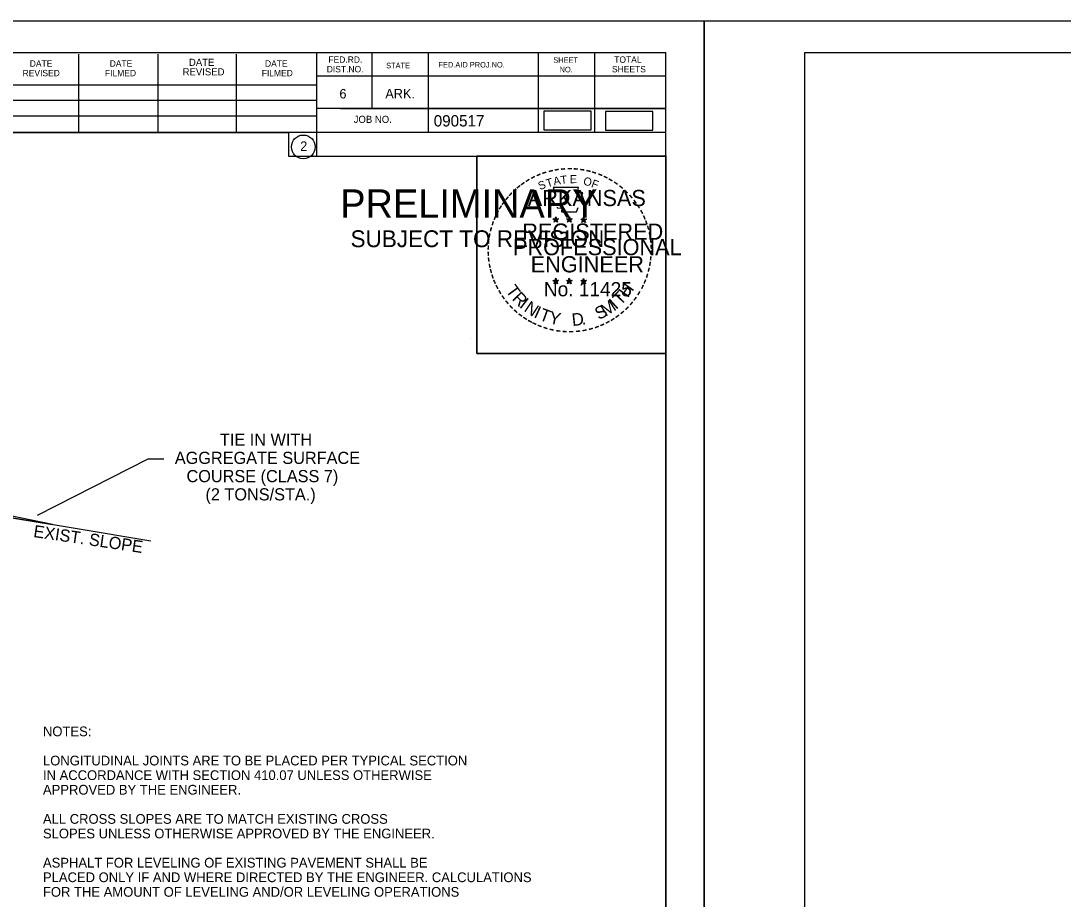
# Model space of a CAD drawing. Extents: x 2263886 to 2266026, y -3122850 to -3121850.
# Drawn here: x 2265483.5 to 2265547.8, y -3122391.3 to -3122337.2 of the extents above; entities that cross this region are included whole.
import ezdxf

# ---------------------------------------------------------------- set-up
doc = ezdxf.new("R2010")
doc.units = 0
for name, color, linetype in [('_CIVIL_CONSTRUCTION', 7, 'Continuous'), ('R_Border PE', 7, 'Continuous'), ('R_Border Prem', 7, 'Continuous'), ('R_Draft', 7, 'Continuous'), ('R_Vert Alg', 7, 'Continuous')]:
    doc.layers.add(name, color=color, linetype=linetype)

msp = doc.modelspace()

# ---------------------------------------------------------------- linework, layer by layer
at = {"layer": '_CIVIL_CONSTRUCTION'}
for p, q in [((2265359.025, -3122337.151), (2265525.692, -3122337.151)), ((2265525.695, -3122337.151), (2265692.362, -3122337.151)), ((2265511.332, -3122356.73), (2265511.332, -3122356.73))]:
    msp.add_line(p, q, dxfattribs=at)
for points in [[(2265359.022, -3122337.151), (2265525.692, -3122337.151), (2265525.692, -3122443.82), (2265359.022, -3122443.82)], [(2265525.692, -3122337.151), (2265692.362, -3122337.151), (2265692.362, -3122443.82), (2265525.692, -3122443.82)], [(2265482.186, -3122339.098), (2265482.186, -3122344.038), (2265500.052, -3122344.038), (2265500.052, -3122345.498), (2265511.651, -3122345.498), (2265511.651, -3122357.664), (2265523.316, -3122357.664), (2265523.316, -3122441.828), (2265365.226, -3122441.828), (2265365.226, -3122339.098)], [(2265648.856, -3122339.098), (2265648.856, -3122344.038), (2265666.722, -3122344.038), (2265666.722, -3122345.498), (2265678.321, -3122345.498), (2265678.321, -3122357.664), (2265689.986, -3122357.664), (2265689.986, -3122441.828), (2265531.896, -3122441.828), (2265531.896, -3122339.098)], [(2265511.651, -3122345.482), (2265523.316, -3122345.482), (2265523.316, -3122357.664), (2265511.651, -3122357.664)]]:
    msp.add_lwpolyline(points, close=True, dxfattribs=at)
at = {"layer": 'R_Border PE'}
for p, q in [((2265516.357, -3122349.375), (2265516.532, -3122349.431)), ((2265516.357, -3122349.375), (2265516.484, -3122349.398)), ((2265516.357, -3122349.375), (2265516.476, -3122349.436)), ((2265516.424, -3122349.579), (2265516.532, -3122349.431)), ((2265516.424, -3122349.579), (2265516.487, -3122349.457)), ((2265516.424, -3122349.579), (2265516.531, -3122349.471)), ((2265516.532, -3122349.248), (2265516.511, -3122349.374)), ((2265516.638, -3122349.579), (2265516.531, -3122349.472)), ((2265516.532, -3122349.431), (2265516.532, -3122349.248)), ((2265516.532, -3122349.248), (2265516.556, -3122349.373)), ((2265516.705, -3122349.375), (2265516.532, -3122349.431)), ((2265516.638, -3122349.579), (2265516.532, -3122349.431)), ((2265516.705, -3122349.375), (2265516.562, -3122349.4)), ((2265516.638, -3122349.579), (2265516.57, -3122349.434)), ((2265516.705, -3122349.375), (2265516.603, -3122349.426)), ((2265517.192, -3122349.375), (2265517.367, -3122349.431)), ((2265517.192, -3122349.375), (2265517.319, -3122349.398)), ((2265517.192, -3122349.375), (2265517.311, -3122349.436)), ((2265517.259, -3122349.579), (2265517.367, -3122349.431)), ((2265517.259, -3122349.579), (2265517.322, -3122349.457)), ((2265517.259, -3122349.579), (2265517.366, -3122349.471)), ((2265517.367, -3122349.248), (2265517.346, -3122349.374)), ((2265517.473, -3122349.579), (2265517.366, -3122349.472)), ((2265517.367, -3122349.431), (2265517.367, -3122349.248)), ((2265517.367, -3122349.248), (2265517.391, -3122349.373)), ((2265517.54, -3122349.375), (2265517.367, -3122349.431)), ((2265517.473, -3122349.579), (2265517.367, -3122349.431)), ((2265517.54, -3122349.375), (2265517.397, -3122349.4)), ((2265517.473, -3122349.579), (2265517.405, -3122349.434)), ((2265517.54, -3122349.375), (2265517.438, -3122349.426)), ((2265518.074, -3122349.381), (2265518.249, -3122349.437)), ((2265518.074, -3122349.381), (2265518.201, -3122349.404)), ((2265518.074, -3122349.381), (2265518.193, -3122349.442)), ((2265518.141, -3122349.585), (2265518.249, -3122349.437)), ((2265518.141, -3122349.585), (2265518.204, -3122349.463)), ((2265518.141, -3122349.585), (2265518.248, -3122349.477)), ((2265518.249, -3122349.254), (2265518.228, -3122349.38)), ((2265518.355, -3122349.585), (2265518.248, -3122349.478)), ((2265518.249, -3122349.437), (2265518.249, -3122349.254)), ((2265518.249, -3122349.254), (2265518.273, -3122349.379)), ((2265518.422, -3122349.381), (2265518.249, -3122349.437)), ((2265518.355, -3122349.585), (2265518.249, -3122349.437)), ((2265518.422, -3122349.381), (2265518.279, -3122349.406)), ((2265518.355, -3122349.585), (2265518.287, -3122349.44)), ((2265518.422, -3122349.381), (2265518.32, -3122349.432)), ((2265516.355, -3122353.162), (2265516.53, -3122353.217)), ((2265516.355, -3122353.162), (2265516.482, -3122353.184)), ((2265516.355, -3122353.162), (2265516.474, -3122353.223)), ((2265516.422, -3122353.366), (2265516.53, -3122353.217)), ((2265516.422, -3122353.366), (2265516.485, -3122353.244)), ((2265516.422, -3122353.366), (2265516.529, -3122353.257)), ((2265516.53, -3122353.035), (2265516.509, -3122353.161)), ((2265516.636, -3122353.366), (2265516.529, -3122353.259)), ((2265516.53, -3122353.217), (2265516.53, -3122353.035)), ((2265516.53, -3122353.035), (2265516.554, -3122353.16)), ((2265516.703, -3122353.162), (2265516.53, -3122353.217)), ((2265516.636, -3122353.366), (2265516.53, -3122353.217)), ((2265516.703, -3122353.162), (2265516.56, -3122353.186)), ((2265516.636, -3122353.366), (2265516.568, -3122353.22)), ((2265516.703, -3122353.162), (2265516.601, -3122353.213)), ((2265517.19, -3122353.162), (2265517.364, -3122353.217)), ((2265517.19, -3122353.162), (2265517.316, -3122353.184)), ((2265517.19, -3122353.162), (2265517.308, -3122353.223)), ((2265517.256, -3122353.366), (2265517.364, -3122353.217)), ((2265517.256, -3122353.366), (2265517.319, -3122353.244)), ((2265517.256, -3122353.366), (2265517.363, -3122353.257)), ((2265517.364, -3122353.035), (2265517.344, -3122353.161)), ((2265517.471, -3122353.366), (2265517.363, -3122353.259)), ((2265517.364, -3122353.217), (2265517.364, -3122353.035)), ((2265517.364, -3122353.035), (2265517.389, -3122353.16)), ((2265517.538, -3122353.162), (2265517.364, -3122353.217)), ((2265517.471, -3122353.366), (2265517.364, -3122353.217)), ((2265517.538, -3122353.162), (2265517.395, -3122353.186)), ((2265517.471, -3122353.366), (2265517.402, -3122353.22)), ((2265517.538, -3122353.162), (2265517.436, -3122353.213)), ((2265518.073, -3122353.167), (2265518.248, -3122353.222)), ((2265518.073, -3122353.167), (2265518.2, -3122353.189)), ((2265518.073, -3122353.167), (2265518.192, -3122353.228)), ((2265518.14, -3122353.371), (2265518.248, -3122353.222)), ((2265518.14, -3122353.371), (2265518.203, -3122353.249)), ((2265518.14, -3122353.371), (2265518.247, -3122353.262)), ((2265518.248, -3122353.04), (2265518.227, -3122353.166)), ((2265518.354, -3122353.371), (2265518.247, -3122353.264)), ((2265518.248, -3122353.222), (2265518.248, -3122353.04)), ((2265518.248, -3122353.04), (2265518.272, -3122353.165)), ((2265518.421, -3122353.167), (2265518.248, -3122353.222)), ((2265518.354, -3122353.371), (2265518.248, -3122353.222)), ((2265518.421, -3122353.167), (2265518.278, -3122353.191)), ((2265518.354, -3122353.371), (2265518.286, -3122353.225)), ((2265518.421, -3122353.167), (2265518.319, -3122353.218))]:
    msp.add_line(p, q, dxfattribs=at)
for points in [[(2265516.378, -3122347.436), (2265516.512, -3122347.85)], [(2265518.133, -3122347.897), (2265518.204, -3122347.755), (2265517.862, -3122347.767), (2265517.936, -3122347.436), (2265516.378, -3122347.436)], [(2265516.624, -3122348.648), (2265516.624, -3122348.691), (2265516.905, -3122348.701), (2265516.878, -3122348.937), (2265517.813, -3122348.937), (2265517.914, -3122348.669)], [(2265516.532, -3122349.248), (2265516.638, -3122349.579), (2265516.357, -3122349.375), (2265516.705, -3122349.375), (2265516.424, -3122349.579), (2265516.532, -3122349.248)], [(2265517.367, -3122349.248), (2265517.473, -3122349.579), (2265517.192, -3122349.375), (2265517.54, -3122349.375), (2265517.259, -3122349.579), (2265517.367, -3122349.248)], [(2265518.249, -3122349.254), (2265518.355, -3122349.585), (2265518.074, -3122349.381), (2265518.422, -3122349.381), (2265518.141, -3122349.585), (2265518.249, -3122349.254)], [(2265516.53, -3122353.035), (2265516.636, -3122353.366), (2265516.355, -3122353.162), (2265516.703, -3122353.162), (2265516.422, -3122353.366), (2265516.53, -3122353.035)], [(2265517.364, -3122353.035), (2265517.471, -3122353.366), (2265517.19, -3122353.162), (2265517.538, -3122353.162), (2265517.256, -3122353.366), (2265517.364, -3122353.035)], [(2265518.248, -3122353.04), (2265518.354, -3122353.371), (2265518.073, -3122353.167), (2265518.421, -3122353.167), (2265518.14, -3122353.371), (2265518.248, -3122353.04)]]:
    msp.add_lwpolyline(points, dxfattribs=at)
for centre, radius in [((2265516.531, -3122349.431), 0.0861), ((2265516.531, -3122349.431), 0.0723), ((2265516.531, -3122349.431), 0.0579), ((2265516.531, -3122349.431), 0.0495), ((2265516.531, -3122349.431), 0.0374), ((2265516.531, -3122349.431), 0.0248), ((2265516.531, -3122349.431), 0.0148), ((2265517.366, -3122349.431), 0.0861), ((2265517.366, -3122349.431), 0.0723), ((2265517.366, -3122349.431), 0.0579), ((2265517.366, -3122349.431), 0.0495), ((2265517.366, -3122349.431), 0.0374), ((2265517.366, -3122349.431), 0.0248), ((2265517.366, -3122349.431), 0.0148), ((2265518.248, -3122349.437), 0.0861), ((2265518.248, -3122349.437), 0.0723), ((2265518.248, -3122349.437), 0.0579), ((2265518.248, -3122349.437), 0.0495), ((2265518.248, -3122349.437), 0.0374), ((2265518.248, -3122349.437), 0.0248), ((2265518.248, -3122349.437), 0.0148), ((2265516.529, -3122353.217), 0.0861), ((2265516.529, -3122353.217), 0.0723), ((2265516.529, -3122353.217), 0.0579), ((2265516.529, -3122353.217), 0.0495), ((2265516.529, -3122353.217), 0.0374), ((2265516.529, -3122353.217), 0.0248), ((2265516.529, -3122353.217), 0.0148), ((2265517.364, -3122353.217), 0.0861), ((2265517.364, -3122353.217), 0.0723), ((2265517.364, -3122353.217), 0.0579), ((2265517.364, -3122353.217), 0.0495), ((2265517.364, -3122353.217), 0.0374), ((2265517.364, -3122353.217), 0.0248), ((2265517.364, -3122353.217), 0.0148), ((2265518.247, -3122353.222), 0.0861), ((2265518.247, -3122353.222), 0.0723), ((2265518.247, -3122353.222), 0.0579), ((2265518.247, -3122353.222), 0.0495), ((2265518.247, -3122353.222), 0.0374), ((2265518.247, -3122353.222), 0.0248), ((2265518.247, -3122353.222), 0.0148)]:
    msp.add_circle(centre, radius, dxfattribs=at)
at = {"layer": 'R_Border Prem'}
for p, q in [((2265485.48, -3122368.228), (2265481.556, -3122367.404)), ((2265491.562, -3122369.242), (2265481.556, -3122367.574)), ((2265481.556, -3122367.574), (2265485.48, -3122368.228))]:
    msp.add_line(p, q, dxfattribs=at)
msp.add_lwpolyline([(2265492.359, -3122364.182), (2265491.359, -3122364.182), (2265484.548, -3122367.669)], dxfattribs=at)
at = {"layer": 'R_Draft'}
for p, q in [((2265365.226, -3122339.098), (2265523.316, -3122339.098)), ((2265487.116, -3122344.038), (2265487.116, -3122339.198)), ((2265491.996, -3122344.038), (2265491.996, -3122339.198)), ((2265496.836, -3122344.038), (2265496.836, -3122339.198)), ((2265501.766, -3122339.098), (2265501.766, -3122345.498)), ((2265505.186, -3122339.098), (2265505.186, -3122342.568)), ((2265508.656, -3122339.098), (2265508.656, -3122344.038)), ((2265515.446, -3122339.098), (2265515.446, -3122344.038)), ((2265518.916, -3122339.098), (2265518.916, -3122344.038)), ((2265523.316, -3122441.828), (2265523.316, -3122339.098)), ((2265531.896, -3122339.098), (2265689.986, -3122339.098)), ((2265531.896, -3122441.828), (2265531.896, -3122339.098)), ((2265482.186, -3122341.108), (2265501.766, -3122341.108)), ((2265523.316, -3122340.568), (2265501.766, -3122340.568)), ((2265523.316, -3122340.558), (2265523.316, -3122340.558)), ((2265482.186, -3122342.038), (2265501.766, -3122342.038)), ((2265482.186, -3122343.008), (2265501.766, -3122343.008)), ((2265523.316, -3122342.568), (2265501.766, -3122342.568)), ((2265503.246, -3122342.568), (2265523.316, -3122342.568)), ((2265523.316, -3122344.038), (2265482.186, -3122344.038)), ((2265501.766, -3122345.498), (2265523.316, -3122345.498))]:
    msp.add_line(p, q, dxfattribs=at)
msp.add_circle((2265500.959, -3122344.93), 0.733, dxfattribs=at)
at = {"layer": 'R_Vert Alg'}
for points in [[(2265515.789, -3122343.868), (2265518.706, -3122343.868), (2265518.706, -3122342.713), (2265515.789, -3122342.713)], [(2265519.604, -3122343.897), (2265522.521, -3122343.897), (2265522.521, -3122342.741), (2265519.604, -3122342.741)]]:
    msp.add_lwpolyline(points, close=True, dxfattribs=at)

# ---------------------------------------------------------------- texts
at = {"layer": 'R_Border PE'}
for s, height, rotation, p in [('-', 0.8, 10.21935, (2265516.465, -3122346.671)), ('-', 0.8, 5.89682, (2265516.83, -3122346.616)), ('-', 0.8, 0.18623, (2265517.216, -3122346.58)), ('-', 0.8, 357.74304, (2265517.577, -3122346.587)), ('-', 0.8, 352.16172, (2265517.949, -3122346.615)), ('-', 0.8, 34.06357, (2265514.819, -3122347.351)), ('-', 0.8, 28.79182, (2265515.118, -3122347.166)), ('-', 0.8, 24.30721, (2265515.434, -3122347.007)), ('-', 0.8, 19.17608, (2265515.751, -3122346.873)), ('T', 0.5, 16.4036, (2265516.012, -3122347.432)), ('-', 0.8, 13.63015, (2265516.126, -3122346.752)), ('A', 0.5, 11.21318, (2265516.425, -3122347.306)), ('T', 0.5, 6.02276, (2265516.849, -3122347.223)), ('E', 0.5, 0.83234, (2265517.402, -3122347.168)), ('O', 0.5, 350.4515, (2265518.204, -3122347.273)), ('-', 0.8, 347.20489, (2265518.309, -3122346.672)), ('F', 0.5, 340.07066, (2265518.681, -3122347.387)), ('-', 0.8, 342.3362, (2265518.626, -3122346.749)), ('-', 0.8, 337.85509, (2265518.994, -3122346.861)), ('-', 0.8, 334.12109, (2265519.309, -3122346.996)), ('-', 0.8, 329.64089, (2265519.599, -3122347.138)), ('-', 0.8, 42.96224, (2265514.076, -3122347.946)), ('-', 0.8, 38.95066, (2265514.292, -3122347.737)), ('-', 0.8, 36.23174, (2265514.53, -3122347.548)), ('S', 0.5, 21.59401, (2265515.555, -3122347.597)), ('-', 0.8, 325.86266, (2265519.92, -3122347.318)), ('-', 0.8, 320.52971, (2265520.225, -3122347.531)), ('-', 0.8, 315.57859, (2265520.525, -3122347.775)), ('-', 0.8, 50.61417, (2265513.65, -3122348.428)), ('-', 0.8, 48.42305, (2265513.852, -3122348.185)), ('-', 0.8, 309.87973, (2265520.809, -3122348.05)), ('-', 0.8, 306.65218, (2265521.072, -3122348.351)), ('-', 0.8, 62.87135, (2265513.125, -3122349.282)), ('-', 0.8, 58.07063, (2265513.281, -3122348.975)), ('-', 0.8, 54.23247, (2265513.444, -3122348.711)), ('-', 0.7, 303.67529, (2265521.315, -3122348.635)), ('-', 0.8, 299.66835, (2265521.474, -3122348.939)), ('-', 0.8, 72.39447, (2265512.886, -3122349.902)), ('-', 0.8, 67.77427, (2265512.995, -3122349.587)), ('-', 0.8, 294.66279, (2265521.636, -3122349.245)), ('-', 0.8, 290.57283, (2265521.765, -3122349.533)), ('-', 0.8, 75.46096, (2265512.787, -3122350.259)), ('-', 0.8, 285.12326, (2265521.882, -3122349.823)), ('-', 0.8, 85.18634, (2265512.683, -3122350.961)), ('-', 0.8, 81.20126, (2265512.721, -3122350.616)), ('-', 0.8, 280.54934, (2265521.982, -3122350.194)), ('-', 0.8, 276.59616, (2265522.063, -3122350.578)), ('-', 0.8, 94.19588, (2265512.688, -3122351.674)), ('-', 0.8, 89.06224, (2265512.671, -3122351.312)), ('-', 0.8, 274.33011, (2265522.093, -3122350.939)), ('-', 0.8, 269.94067, (2265522.11, -3122351.255)), ('-', 0.8, 98.94793, (2265512.724, -3122352.008)), ('-', 0.8, 260.99529, (2265522.065, -3122351.915)), ('-', 0.8, 263.5172, (2265522.1, -3122351.588)), ('-', 0.8, 101.71495, (2265512.792, -3122352.374)), ('-', 0.8, 105.45785, (2265512.873, -3122352.672)), ('-', 0.8, 252.86809, (2265521.919, -3122352.614)), ('-', 0.8, 255.7626, (2265522.01, -3122352.254)), ('-', 0.8, 109.08742, (2265512.98, -3122352.987)), ('-', 0.8, 114.06432, (2265513.107, -3122353.285)), ('T', 0.77, 306.04056, (2265513.409, -3122353.798)), ('H', 0.77, 54.60883, (2265520.969, -3122354.28)), ('-', 0.8, 247.88866, (2265521.808, -3122352.951)), ('-', 0.8, 115.72885, (2265513.26, -3122353.594)), ('-', 0.8, 120.44712, (2265513.438, -3122353.887)), ('R', 0.77, 314.00497, (2265513.791, -3122354.322)), ('T', 0.77, 46.64442, (2265520.525, -3122354.752)), ('-', 0.8, 239.07125, (2265521.48, -3122353.641)), ('-', 0.8, 244.61971, (2265521.677, -3122353.265)), ('-', 0.8, 125.89344, (2265513.64, -3122354.168)), ('-', 0.8, 130.71812, (2265513.871, -3122354.444)), ('I', 0.77, 321.96938, (2265514.241, -3122354.788)), ('N', 0.77, 326.50021, (2265514.524, -3122355.024)), ('M', 0.77, 32.65632, (2265519.602, -3122355.414)), ('I', 0.77, 42.11359, (2265520.244, -3122354.991)), ('-', 0.8, 231.25377, (2265521.064, -3122354.251)), ('-', 0.8, 233.84524, (2265521.279, -3122353.968)), ('-', 0.8, 134.22381, (2265514.129, -3122354.716)), ('-', 0.8, 138.93382, (2265514.392, -3122354.948)), ('-', 0.8, 144.64634, (2265514.67, -3122355.151)), ('I', 0.77, 335.36034, (2265515.129, -3122355.417)), ('T', 0.77, 339.89117, (2265515.459, -3122355.58)), ('Y', 0.77, 347.85558, (2265516.068, -3122355.803)), ('D', 0.77, 6.39691, (2265517.56, -3122355.982)), ('S', 0.77, 26.9312, (2265519.182, -3122355.617)), ('-', 0.8, 215.73633, (2265520.289, -3122355.023)), ('-', 0.8, 221.08509, (2265520.563, -3122354.787)), ('-', 0.8, 225.76533, (2265520.824, -3122354.533)), ('-', 0.8, 148.08978, (2265514.95, -3122355.337)), ('-', 0.8, 151.57039, (2265515.24, -3122355.499)), ('-', 0.8, 154.60019, (2265515.501, -3122355.623)), ('-', 0.8, 158.56121, (2265515.813, -3122355.75)), ('.', 0.77, 13.76417, (2265518.156, -3122355.919)), ('-', 0.8, 200.71842, (2265519.121, -3122355.686)), ('-', 0.8, 204.25161, (2265519.431, -3122355.549)), ('-', 0.8, 207.35684, (2265519.743, -3122355.39)), ('-', 0.8, 212.24909, (2265520.022, -3122355.217)), ('-', 0.8, 162.79826, (2265516.156, -3122355.856)), ('-', 0.8, 167.55551, (2265516.514, -3122355.938)), ('-', 0.8, 173.11546, (2265516.9, -3122355.993)), ('-', 0.8, 176.51827, (2265517.274, -3122356.02)), ('-', 0.8, 181.59176, (2265517.646, -3122356.01)), ('-', 0.8, 185.81666, (2265518.05, -3122355.972)), ('-', 0.8, 191.28576, (2265518.418, -3122355.906)), ('-', 0.8, 195.47429, (2265518.783, -3122355.807))]:
    msp.add_text(s, height=height, rotation=rotation, dxfattribs=at).set_placement(p)
for s, height, p in [('ARKANSAS', 1, (2265514.804, -3122348.58)), ('DWB', 0.005, (2265516.525, -3122349.433)), ('DWB', 0.005, (2265517.36, -3122349.433)), ('DWB', 0.005, (2265518.242, -3122349.439)), ('REGISTERED', 1, (2265514.465, -3122350.655)), ('PROFESSIONAL', 1, (2265513.891, -3122351.607)), ('ENGINEER', 1, (2265514.984, -3122352.669)), ('No. 11425', 0.8785, (2265515.798, -3122354.145)), ('DWB', 0.005, (2265516.523, -3122353.22)), ('DWB', 0.005, (2265517.358, -3122353.219)), ('DWB', 0.005, (2265518.241, -3122353.224))]:
    msp.add_text(s, height=height, dxfattribs=at).set_placement(p)
at = {"layer": 'R_Border Prem'}
for s, height, p in [('PRELIMINARY', 1.75, (2265503.235, -3122349.298)), ('DWB', 0.005, (2265503.341, -3122348.374)), ('SUBJECT TO REVISION', 1.03756, (2265503.872, -3122351.112)), ('TIE IN WITH ', 0.75, (2265495.816, -3122363.361)), ('AGGREGATE SURFACE', 0.75, (2265493.034, -3122364.486)), ('COURSE (CLASS 7)', 0.75, (2265493.755, -3122365.611)), ('(2 TONS/STA.)', 0.75, (2265494.924, -3122366.736)), ('NOTES: ', 0.6, (2265484.901, -3122381.285)), ('LONGITUDINAL JOINTS ARE TO BE PLACED PER TYPICAL SECTION', 0.6, (2265484.901, -3122383.085)), ('IN ACCORDANCE WITH SECTION 410.07 UNLESS OTHERWISE', 0.6, (2265484.901, -3122383.985)), ('APPROVED BY THE ENGINEER.', 0.6, (2265484.901, -3122384.885)), ('ALL CROSS SLOPES ARE TO MATCH EXISTING CROSS ', 0.6, (2265484.901, -3122386.685)), ('SLOPES UNLESS OTHERWISE APPROVED BY THE ENGINEER.', 0.6, (2265484.901, -3122387.585)), ('ASPHALT FOR LEVELING OF EXISTING PAVEMENT SHALL BE', 0.6, (2265484.901, -3122389.385)), ('PLACED ONLY IF AND WHERE DIRECTED BY THE ENGINEER. CALCULATIONS', 0.6, (2265484.901, -3122390.285)), ('FOR THE AMOUNT OF LEVELING AND/OR LEVELING OPERATIONS', 0.6, (2265484.901, -3122391.185))]:
    msp.add_text(s, height=height, dxfattribs=at).set_placement(p)
msp.add_text('EXIST. SLOPE', height=0.75, rotation=351.57554, dxfattribs=at).set_placement((2265484.28, -3122368.99))
at = {"layer": 'R_Draft'}
for s, height, p in [('DATE', 0.391, (2265484.086, -3122339.978)), ('DATE', 0.391, (2265489.016, -3122339.978)), ('DATE', 0.4396, (2265493.906, -3122339.928)), ('DATE', 0.391, (2265498.596, -3122339.978)), ('FED.RD.', 0.391, (2265502.506, -3122339.738)), ('STATE', 0.342, (2265506.066, -3122340.078)), ('FED.AID PROJ.NO.', 0.342, (2265509.296, -3122340.028)), ('SHEET', 0.342, (2265516.376, -3122339.738)), ('TOTAL', 0.391, (2265520.136, -3122339.738)), ('REVISED', 0.391, (2265483.646, -3122340.568)), ('FILMED', 0.391, (2265488.726, -3122340.568)), ('REVISED', 0.4396, (2265493.516, -3122340.518)), ('FILMED', 0.391, (2265498.396, -3122340.568)), ('DIST.NO.', 0.391, (2265502.406, -3122340.328)), ('NO.', 0.342, (2265516.766, -3122340.328)), ('SHEETS', 0.391, (2265519.996, -3122340.328)), ('6', 0.586, (2265503.186, -3122341.938)), ('ARK.', 0.5861, (2265506.016, -3122341.938)), ('JOB NO.', 0.4396, (2265504.066, -3122343.448)), ('090517', 0.7, (2265509.004, -3122343.668)), ('2', 0.586, (2265500.768, -3122345.173))]:
    msp.add_text(s, height=height, dxfattribs=at).set_placement(p)

doc.saveas('drawing.dxf')
